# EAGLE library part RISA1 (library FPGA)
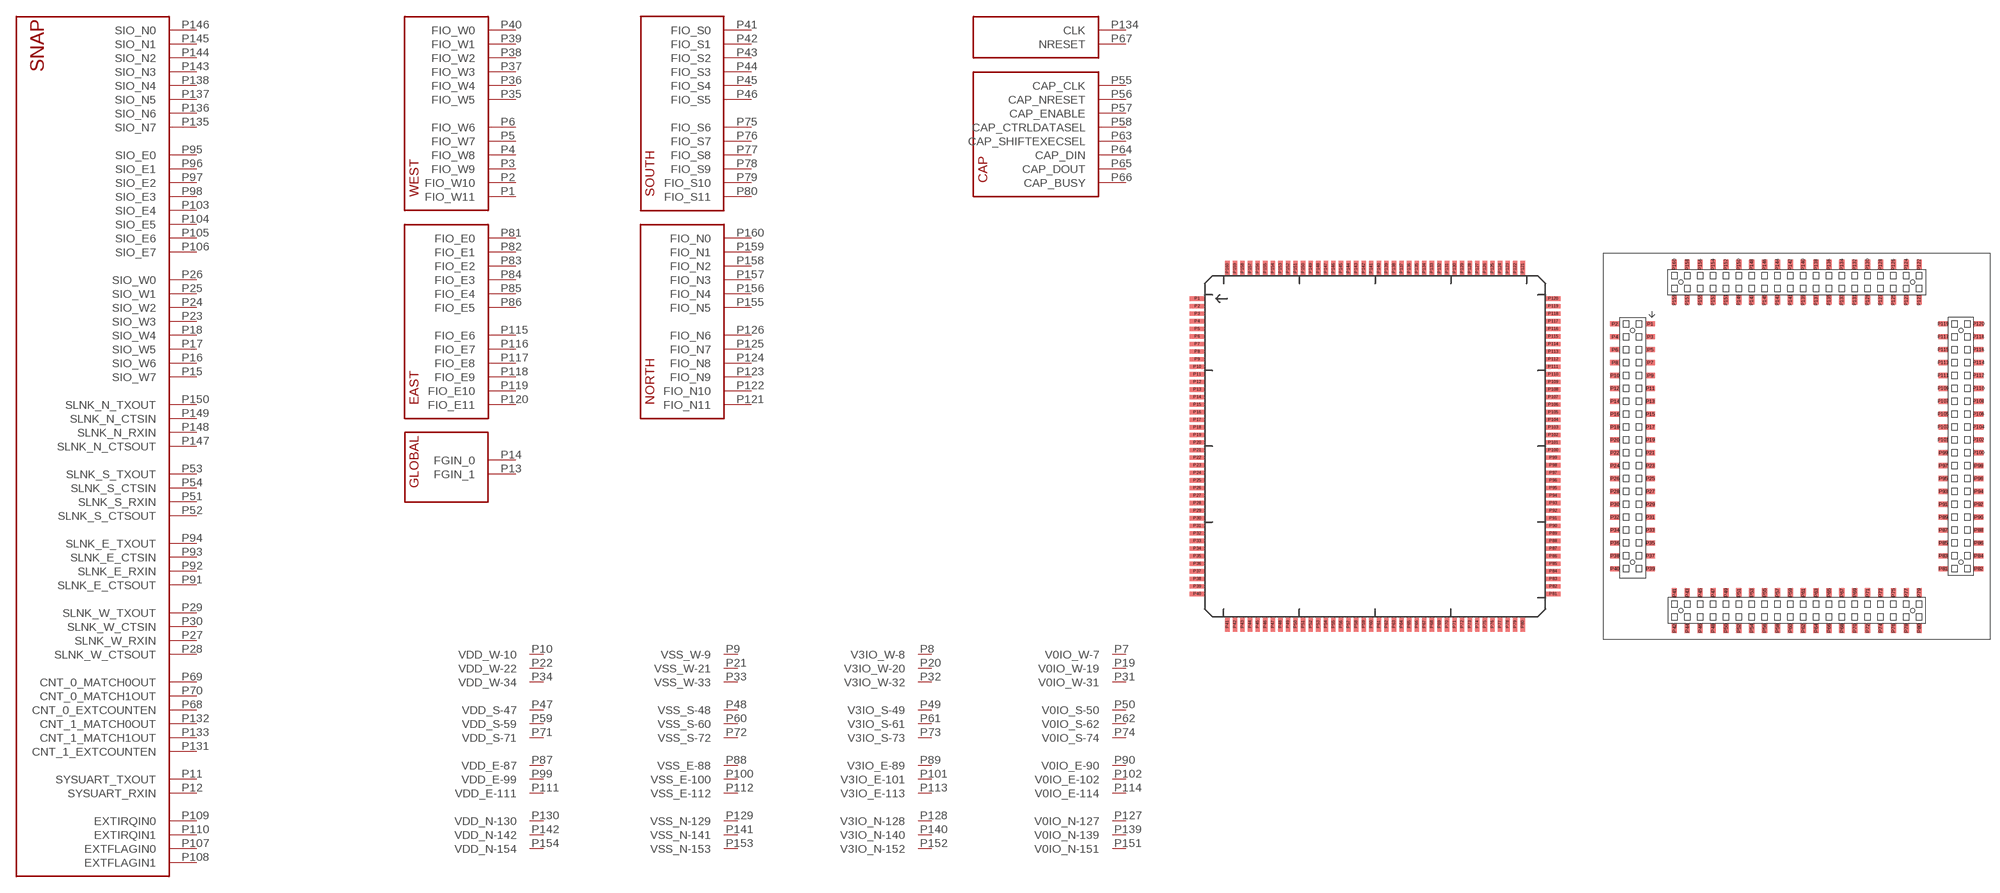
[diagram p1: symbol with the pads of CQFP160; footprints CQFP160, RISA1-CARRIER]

Designator prefix -; gates FPGA=RISA1-FPGA PWR=RISA1-PWR SNAP=RISA1-SNAP SYSTEM=RISA1-SYSTEM

## RISA1CHIP  [CQFP160]
P1  FPGA:FIO_W11
P2  FPGA:FIO_W10
P3  FPGA:FIO_W9
P4  FPGA:FIO_W8
P5  FPGA:FIO_W7
P6  FPGA:FIO_W6
P7  PWR:V0IO_W-7  pwr
P8  PWR:V3IO_W-8  pwr
P9  PWR:VSS_W-9  pwr
P10  PWR:VDD_W-10  pwr
P11  SNAP:SYSUART_TXOUT  out
P12  SNAP:SYSUART_RXIN  in
P13  FPGA:FGIN_1  in
P14  FPGA:FGIN_0  in
P15  SNAP:SIO_W7
P16  SNAP:SIO_W6
P17  SNAP:SIO_W5
P18  SNAP:SIO_W4
P19  PWR:V0IO_W-19  pwr
P20  PWR:V3IO_W-20  pwr
P21  PWR:VSS_W-21  pwr
P22  PWR:VDD_W-22  pwr
P23  SNAP:SIO_W3
P24  SNAP:SIO_W2
P25  SNAP:SIO_W1
P26  SNAP:SIO_W0
P27  SNAP:SLNK_W_RXIN  in
P28  SNAP:SLNK_W_CTSOUT  out
P29  SNAP:SLNK_W_TXOUT  out
P30  SNAP:SLNK_W_CTSIN  in
P31  PWR:V0IO_W-31  pwr
P32  PWR:V3IO_W-32  pwr
P33  PWR:VSS_W-33  pwr
P34  PWR:VDD_W-34  pwr
P35  FPGA:FIO_W5
P36  FPGA:FIO_W4
P37  FPGA:FIO_W3
P38  FPGA:FIO_W2
P39  FPGA:FIO_W1
P40  FPGA:FIO_W0
P41  FPGA:FIO_S0
P42  FPGA:FIO_S1
P43  FPGA:FIO_S2
P44  FPGA:FIO_S3
P45  FPGA:FIO_S4
P46  FPGA:FIO_S5
P47  PWR:VDD_S-47  pwr
P48  PWR:VSS_S-48  pwr
P49  PWR:V3IO_S-49  pwr
P50  PWR:V0IO_S-50  pwr
P51  SNAP:SLNK_S_RXIN  in
P52  SNAP:SLNK_S_CTSOUT  out
P53  SNAP:SLNK_S_TXOUT  out
P54  SNAP:SLNK_S_CTSIN  in
P55  SYSTEM:CAP_CLK  in
P56  SYSTEM:CAP_NRESET  in
P57  SYSTEM:CAP_ENABLE  in
P58  SYSTEM:CAP_CTRLDATASEL  in
P59  PWR:VDD_S-59  pwr
P60  PWR:VSS_S-60  pwr
P61  PWR:V3IO_S-61  pwr
P62  PWR:V0IO_S-62  pwr
P63  SYSTEM:CAP_SHIFTEXECSEL  in
P64  SYSTEM:CAP_DIN  in
P65  SYSTEM:CAP_DOUT  out
P66  SYSTEM:CAP_BUSY  out
P67  SYSTEM:NRESET  in
P68  SNAP:CNT_0_EXTCOUNTEN  in
P69  SNAP:CNT_0_MATCH0OUT  out
P70  SNAP:CNT_0_MATCH1OUT  out
P71  PWR:VDD_S-71  pwr
P72  PWR:VSS_S-72  pwr
P73  PWR:V3IO_S-73  pwr
P74  PWR:V0IO_S-74  pwr
P75  FPGA:FIO_S6
P76  FPGA:FIO_S7
P77  FPGA:FIO_S8
P78  FPGA:FIO_S9
P79  FPGA:FIO_S10
P80  FPGA:FIO_S11
P81  FPGA:FIO_E0
P82  FPGA:FIO_E1
P83  FPGA:FIO_E2
P84  FPGA:FIO_E3
P85  FPGA:FIO_E4
P86  FPGA:FIO_E5
P87  PWR:VDD_E-87  pwr
P88  PWR:VSS_E-88  pwr
P89  PWR:V3IO_E-89  pwr
P90  PWR:V0IO_E-90  pwr
P91  SNAP:SLNK_E_CTSOUT  out
P92  SNAP:SLNK_E_RXIN  in
P93  SNAP:SLNK_E_CTSIN  in
P94  SNAP:SLNK_E_TXOUT  out
P95  SNAP:SIO_E0
P96  SNAP:SIO_E1
P97  SNAP:SIO_E2
P98  SNAP:SIO_E3
P99  PWR:VDD_E-99  pwr
P100  PWR:VSS_E-100  pwr
P101  PWR:V3IO_E-101  pwr
P102  PWR:V0IO_E-102  pwr
P103  SNAP:SIO_E4
P104  SNAP:SIO_E5
P105  SNAP:SIO_E6
P106  SNAP:SIO_E7
P107  SNAP:EXTFLAGIN0  in
P108  SNAP:EXTFLAGIN1  in
P109  SNAP:EXTIRQIN0  in
P110  SNAP:EXTIRQIN1  in
P111  PWR:VDD_E-111  pwr
P112  PWR:VSS_E-112  pwr
P113  PWR:V3IO_E-113  pwr
P114  PWR:V0IO_E-114  pwr
P115  FPGA:FIO_E6
P116  FPGA:FIO_E7
P117  FPGA:FIO_E8
P118  FPGA:FIO_E9
P119  FPGA:FIO_E10
P120  FPGA:FIO_E11
P121  FPGA:FIO_N11
P122  FPGA:FIO_N10
P123  FPGA:FIO_N9
P124  FPGA:FIO_N8
P125  FPGA:FIO_N7
P126  FPGA:FIO_N6
P127  PWR:V0IO_N-127  pwr
P128  PWR:V3IO_N-128  pwr
P129  PWR:VSS_N-129  pwr
P130  PWR:VDD_N-130  pwr
P131  SNAP:CNT_1_EXTCOUNTEN  in
P132  SNAP:CNT_1_MATCH0OUT  out
P133  SNAP:CNT_1_MATCH1OUT  out
P134  SYSTEM:CLK  in
P135  SNAP:SIO_N7
P136  SNAP:SIO_N6
P137  SNAP:SIO_N5
P138  SNAP:SIO_N4
P139  PWR:V0IO_N-139  pwr
P140  PWR:V3IO_N-140  pwr
P141  PWR:VSS_N-141  pwr
P142  PWR:VDD_N-142  pwr
P143  SNAP:SIO_N3
P144  SNAP:SIO_N2
P145  SNAP:SIO_N1
P146  SNAP:SIO_N0
P147  SNAP:SLNK_N_CTSOUT  out
P148  SNAP:SLNK_N_RXIN  in
P149  SNAP:SLNK_N_CTSIN  in
P150  SNAP:SLNK_N_TXOUT  out
P151  PWR:V0IO_N-151  pwr
P152  PWR:V3IO_N-152  pwr
P153  PWR:VSS_N-153  pwr
P154  PWR:VDD_N-154  pwr
P155  FPGA:FIO_N5
P156  FPGA:FIO_N4
P157  FPGA:FIO_N3
P158  FPGA:FIO_N2
P159  FPGA:FIO_N1
P160  FPGA:FIO_N0

## RISA1CARRIER  [RISA1-CARRIER]
Pads as for CQFP160

## Footprint CQFP160 (pad centres in mm)
smd 1.27 x 0.381: P1 -15.281,12.68; P2 -15.281,12.03; P3 -15.281,11.379; P4 -15.281,10.729; P5 -15.281,10.079; P6 -15.281,9.428; P7 -15.281,8.778; P8 -15.281,8.128; P9 -15.281,7.478; P10 -15.281,6.828; P11 -15.281,6.177; P12 -15.281,5.527; P13 -15.281,4.877; P14 -15.281,4.227; P15 -15.281,3.576; P16 -15.281,2.926; P17 -15.281,2.276; P18 -15.281,1.626; P19 -15.281,0.975; P20 -15.281,0.325; P21 -15.281,-0.325; P22 -15.281,-0.975; P23 -15.281,-1.625; P24 -15.281,-2.276; P25 -15.281,-2.926; P26 -15.281,-3.576; P27 -15.281,-4.226; P28 -15.281,-4.877; P29 -15.281,-5.527; P30 -15.281,-6.177; P31 -15.281,-6.827; P32 -15.281,-7.478; P33 -15.281,-8.128; P34 -15.281,-8.778; P35 -15.281,-9.428; P36 -15.281,-10.079; P37 -15.281,-10.729; P38 -15.281,-11.379; P39 -15.281,-12.029; P40 -15.281,-12.68; P81 15.281,-12.68; P82 15.281,-12.029; P83 15.281,-11.379; P84 15.281,-10.729; P85 15.281,-10.079; P86 15.281,-9.428; P87 15.281,-8.778; P88 15.281,-8.128; P89 15.281,-7.478; P90 15.281,-6.827; P91 15.281,-6.177; P92 15.281,-5.527; P93 15.281,-4.877; P94 15.281,-4.226; P95 15.281,-3.576; P96 15.281,-2.926; P97 15.281,-2.276; P98 15.281,-1.625; P99 15.281,-0.975; P100 15.281,-0.325; P101 15.281,0.325; P102 15.281,0.975; P103 15.281,1.626; P104 15.281,2.276; P105 15.281,2.926; P106 15.281,3.576; P107 15.281,4.227; P108 15.281,4.877; P109 15.281,5.527; P110 15.281,6.177; P111 15.281,6.828; P112 15.281,7.478; P113 15.281,8.128; P114 15.281,8.778; P115 15.281,9.428; P116 15.281,10.079; P117 15.281,10.729; P118 15.281,11.379; P119 15.281,12.03; P120 15.281,12.68
smd 0.381 x 1.27: P41 -12.68,-15.281; P42 -12.03,-15.281; P43 -11.379,-15.281; P44 -10.729,-15.281; P45 -10.079,-15.281; P46 -9.428,-15.281; P47 -8.778,-15.281; P48 -8.128,-15.281; P49 -7.478,-15.281; P50 -6.828,-15.281; P51 -6.177,-15.281; P52 -5.527,-15.281; P53 -4.877,-15.281; P54 -4.227,-15.281; P55 -3.576,-15.281; P56 -2.926,-15.281; P57 -2.276,-15.281; P58 -1.626,-15.281; P59 -0.975,-15.281; P60 -0.325,-15.281; P61 0.325,-15.281; P62 0.975,-15.281; P63 1.626,-15.281; P64 2.276,-15.281; P65 2.926,-15.281; P66 3.576,-15.281; P67 4.226,-15.281; P68 4.877,-15.281; P69 5.527,-15.281; P70 6.177,-15.281; P71 6.827,-15.281; P72 7.478,-15.281; P73 8.128,-15.281; P74 8.778,-15.281; P75 9.428,-15.281; P76 10.079,-15.281; P77 10.729,-15.281; P78 11.379,-15.281; P79 12.029,-15.281; P80 12.68,-15.281; P121 12.68,15.281; P122 12.029,15.281; P123 11.379,15.281; P124 10.729,15.281; P125 10.079,15.281; P126 9.428,15.281; P127 8.778,15.281; P128 8.128,15.281; P129 7.478,15.281; P130 6.827,15.281; P131 6.177,15.281; P132 5.527,15.281; P133 4.877,15.281; P134 4.226,15.281; P135 3.576,15.281; P136 2.926,15.281; P137 2.276,15.281; P138 1.626,15.281; P139 0.975,15.281; P140 0.325,15.281; P141 -0.325,15.281; P142 -0.975,15.281; P143 -1.626,15.281; P144 -2.276,15.281; P145 -2.926,15.281; P146 -3.576,15.281; P147 -4.227,15.281; P148 -4.877,15.281; P149 -5.527,15.281; P150 -6.177,15.281; P151 -6.828,15.281; P152 -7.478,15.281; P153 -8.128,15.281; P154 -8.778,15.281; P155 -9.428,15.281; P156 -10.079,15.281; P157 -10.729,15.281; P158 -11.379,15.281; P159 -12.03,15.281; P160 -12.68,15.281

## Footprint RISA1-CARRIER (pad centres in mm)
smd 1.5 x 0.8: P1 -22.75,19; P2 -28.25,19; P3 -22.75,17; P4 -28.25,17; P5 -22.75,15; P6 -28.25,15; P7 -22.75,13; P8 -28.25,13; P9 -22.75,11; P10 -28.25,11; P11 -22.75,9; P12 -28.25,9; P13 -22.75,7; P14 -28.25,7; P15 -22.75,5; P16 -28.25,5; P17 -22.75,3; P18 -28.25,3; P19 -22.75,1; P20 -28.25,1; P21 -22.75,-1; P22 -28.25,-1; P23 -22.75,-3; P24 -28.25,-3; P25 -22.75,-5; P26 -28.25,-5; P27 -22.75,-7; P28 -28.25,-7; P29 -22.75,-9; P30 -28.25,-9; P31 -22.75,-11; P32 -28.25,-11; P33 -22.75,-13; P34 -28.25,-13; P35 -22.75,-15; P36 -28.25,-15; P37 -22.75,-17; P38 -28.25,-17; P39 -22.75,-19; P40 -28.25,-19; P81 22.75,-19; P82 28.25,-19; P83 22.75,-17; P84 28.25,-17; P85 22.75,-15; P86 28.25,-15; P87 22.75,-13; P88 28.25,-13; P89 22.75,-11; P90 28.25,-11; P91 22.75,-9; P92 28.25,-9; P93 22.75,-7; P94 28.25,-7; P95 22.75,-5; P96 28.25,-5; P97 22.75,-3; P98 28.25,-3; P99 22.75,-1; P100 28.25,-1; P101 22.75,1; P102 28.25,1; P103 22.75,3; P104 28.25,3; P105 22.75,5; P106 28.25,5; P107 22.75,7; P108 28.25,7; P109 22.75,9; P110 28.25,9; P111 22.75,11; P112 28.25,11; P113 22.75,13; P114 28.25,13; P115 22.75,15; P116 28.25,15; P117 22.75,17; P118 28.25,17; P119 22.75,19; P120 28.25,19
smd 0.8 x 1.5: P41 -19,-22.75; P42 -19,-28.25; P43 -17,-22.75; P44 -17,-28.25; P45 -15,-22.75; P46 -15,-28.25; P47 -13,-22.75; P48 -13,-28.25; P49 -11,-22.75; P50 -11,-28.25; P51 -9,-22.75; P52 -9,-28.25; P53 -7,-22.75; P54 -7,-28.25; P55 -5,-22.75; P56 -5,-28.25; P57 -3,-22.75; P58 -3,-28.25; P59 -1,-22.75; P60 -1,-28.25; P61 1,-22.75; P62 1,-28.25; P63 3,-22.75; P64 3,-28.25; P65 5,-22.75; P66 5,-28.25; P67 7,-22.75; P68 7,-28.25; P69 9,-22.75; P70 9,-28.25; P71 11,-22.75; P72 11,-28.25; P73 13,-22.75; P74 13,-28.25; P75 15,-22.75; P76 15,-28.25; P77 17,-22.75; P78 17,-28.25; P79 19,-22.75; P80 19,-28.25; P121 19,22.75; P122 19,28.25; P123 17,22.75; P124 17,28.25; P125 15,22.75; P126 15,28.25; P127 13,22.75; P128 13,28.25; P129 11,22.75; P130 11,28.25; P131 9,22.75; P132 9,28.25; P133 7,22.75; P134 7,28.25; P135 5,22.75; P136 5,28.25; P137 3,22.75; P138 3,28.25; P139 1,22.75; P140 1,28.25; P141 -1,22.75; P142 -1,28.25; P143 -3,22.75; P144 -3,28.25; P145 -5,22.75; P146 -5,28.25; P147 -7,22.75; P148 -7,28.25; P149 -9,22.75; P150 -9,28.25; P151 -11,22.75; P152 -11,28.25; P153 -13,22.75; P154 -13,28.25; P155 -15,22.75; P156 -15,28.25; P157 -17,22.75; P158 -17,28.25; P159 -19,22.75; P160 -19,28.25
hole 0.7 at -25.5,18
hole 0.7 at -25.5,-18
hole 0.7 at -18,-25.5
hole 0.7 at 18,-25.5
hole 0.7 at 25.5,-18
hole 0.7 at 25.5,18
hole 0.7 at 18,25.5
hole 0.7 at -18,25.5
